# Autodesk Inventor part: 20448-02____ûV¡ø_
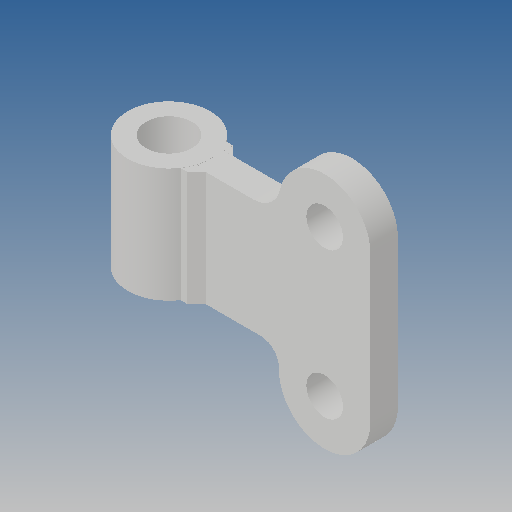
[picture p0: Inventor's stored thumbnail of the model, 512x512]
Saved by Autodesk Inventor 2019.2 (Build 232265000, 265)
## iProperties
Created: 2010-06
Part Number: 20448-02____ûV¡ø_
Material: Ogólny
Document SubType Name: Modeling
Designer: CADENGINEERING4
Density: 1 g/cm^3
Appearance: Domyślna
Author: CADENGINEERING4
Revision Number: ANY
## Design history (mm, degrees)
feature "NONE"
feature "NONE:1"
feature "NONE:2"
feature "NONE:3"
feature "NONE:4"
feature "NONE:5"
node "Bryła1"
node "Bryła2"
node "Bryła3"
node "Bryła4"
node "Bryła5"
node "Bryła6"
